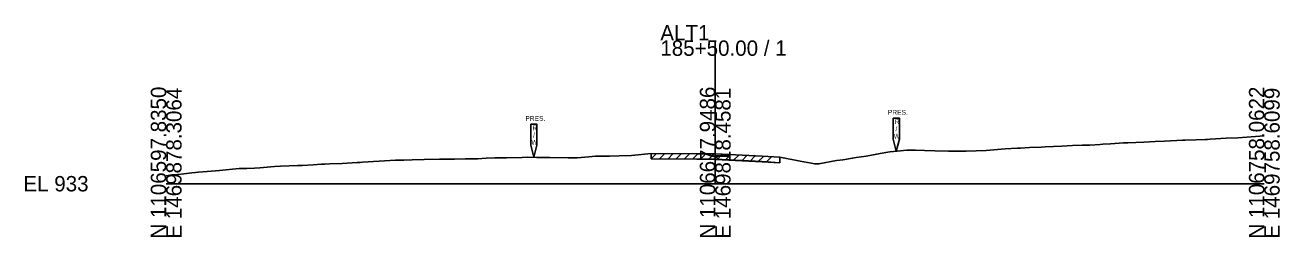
# Model space of a CAD drawing. Extents: x -26 to 2203, y -10 to 19568.
# Drawn here: x 1974.3 to 2202.8, y 7490.3 to 7528.9 of the extents above; entities that cross this region are included whole.
import ezdxf

# ---------------------------------------------------------------- set-up
doc = ezdxf.new("R2010")
doc.units = 0
for name, color, linetype in [('RD_GPK_XS_Cell', 7, 'Continuous'), ('RD_XS_ExGround', 7, 'Continuous'), ('RD_XS_ExPaveRet', 7, 'Continuous'), ('RD_XS_ExRW', 7, 'Continuous')]:
    doc.layers.add(name, color=color, linetype=linetype)

msp = doc.modelspace()

# ---------------------------------------------------------------- linework, layer by layer
at = {"layer": 'RD_GPK_XS_Cell'}
for p, q in [((2100, 7500), (2100, 7526.1)), ((2000, 7500), (2100, 7500)), ((2100, 7500), (2200, 7500))]:
    msp.add_line(p, q, dxfattribs=at)
at = {"layer": 'RD_XS_ExGround'}
msp.add_lwpolyline([(2000, 7501.43), (2001.05, 7501.62), (2002.08, 7501.67), (2003.19, 7501.77), (2004.69, 7501.98), (2005.34, 7502.05), (2005.82, 7502.11), (2007.48, 7502.23), (2009.7, 7502.39), (2013.31, 7502.75), (2014.71, 7502.79), (2016.06, 7502.82), (2017.06, 7502.88), (2019.73, 7503.12), (2020.8, 7503.19), (2023.97, 7503.3), (2024.74, 7503.33), (2026.77, 7503.43), (2028.29, 7503.57), (2028.92, 7503.59), (2029.75, 7503.62), (2032.04, 7503.69), (2034.77, 7503.87), (2035.35, 7503.85), (2035.78, 7503.91), (2038.78, 7504.09), (2039.78, 7504.14), (2041.78, 7504.28), (2043.27, 7504.31), (2044.79, 7504.38), (2047.01, 7504.42), (2049.8, 7504.46), (2050.76, 7504.48), (2052.49, 7504.48), (2054.5, 7504.54), (2054.82, 7504.54), (2056.78, 7504.56), (2058.25, 7504.63), (2059.83, 7504.69), (2061.99, 7504.72), (2064.84, 7504.8), (2065.74, 7504.83), (2067.5, 7504.8), (2069.48, 7504.77), (2069.85, 7504.77), (2073.23, 7504.71), (2074.87, 7504.73), (2076.97, 7504.89), (2078.22, 7504.99), (2079.88, 7505.03), (2080.36, 7505.03), (2080.72, 7505.04), (2082.5, 7505.05), (2084.72, 7505.14), (2088.34, 7505.52), (2096.79, 7505.47), (2100.05, 7505.44), (2108.57, 7505), (2111.75, 7504.82), (2115.49, 7504.1), (2118.13, 7503.62), (2118.48, 7503.62), (2118.87, 7503.62), (2122.11, 7504.2), (2123.23, 7504.36), (2124.99, 7504.67), (2125.65, 7504.78), (2127.51, 7505.03), (2129.4, 7505.39), (2130.01, 7505.5), (2131.8, 7505.79), (2133.14, 7505.96), (2134.89, 7506.14), (2136.46, 7506.11), (2138.09, 7506.06), (2140, 7506.02), (2142.46, 7505.92), (2143.17, 7505.92), (2144.67, 7505.91), (2145.14, 7505.92), (2145.69, 7505.94), (2149.34, 7506.08), (2152.81, 7506.34), (2155.07, 7506.48), (2155.61, 7506.5), (2157.21, 7506.57), (2159.35, 7506.66), (2160.08, 7506.69), (2163.1, 7506.84), (2165.09, 7506.96), (2166.84, 7507.01), (2168.24, 7507.03), (2170.11, 7507.16), (2170.59, 7507.2), (2172.01, 7507.29), (2174.33, 7507.42), (2174.67, 7507.44), (2175.12, 7507.46), (2178.08, 7507.54), (2180.13, 7507.67), (2181.82, 7507.78), (2185.15, 7507.92), (2185.57, 7507.93), (2187.53, 7508), (2189.31, 7508.07), (2189.67, 7508.08), (2190.16, 7508.11), (2193.06, 7508.3), (2195.17, 7508.38), (2196.8, 7508.46), (2200, 7508.7)], dxfattribs=at)
at = {"layer": 'RD_XS_ExPaveRet'}
for p, q in [((2088.34, 7505.52), (2088.34, 7504.52)), ((2088.34, 7504.53), (2089.31, 7505.51)), ((2088.34, 7504.53), (2088.34, 7505.51)), ((2089.84, 7504.51), (2090.83, 7505.5)), ((2091.34, 7504.5), (2092.33, 7505.49)), ((2092.84, 7504.49), (2093.83, 7505.48)), ((2094.34, 7504.49), (2095.33, 7505.47)), ((2095.84, 7504.48), (2096.83, 7505.47)), ((2097.34, 7504.48), (2098.31, 7505.45)), ((2098.84, 7504.47), (2099.81, 7505.44)), ((2100.34, 7504.43), (2101.28, 7505.37)), ((2101.84, 7504.35), (2102.78, 7505.29)), ((2103.34, 7504.27), (2104.28, 7505.22)), ((2104.84, 7504.19), (2105.78, 7505.14)), ((2106.34, 7504.11), (2107.28, 7505.06)), ((2088.34, 7504.53), (2088.36, 7504.54)), ((2088.34, 7504.52), (2096.79, 7504.47)), ((2088.36, 7504.54), (2096.66, 7504.49)), ((2096.66, 7504.49), (2100.07, 7504.46)), ((2096.79, 7504.47), (2100.05, 7504.44)), ((2100.05, 7504.44), (2108.57, 7504)), ((2100.07, 7504.46), (2108.46, 7504.02)), ((2107.84, 7504.04), (2108.78, 7504.98)), ((2108.46, 7504.02), (2111.75, 7503.83)), ((2108.57, 7504), (2111.75, 7503.82)), ((2109.34, 7503.97), (2110.27, 7504.9)), ((2111.75, 7504.83), (2111.75, 7503.83)), ((2111.75, 7504.82), (2111.75, 7503.82))]:
    msp.add_line(p, q, dxfattribs=at)
at = {"layer": 'RD_XS_ExRW'}
for points in [[(2132.43, 7511.95), (2133.53, 7511.95), (2133.53, 7508.12), (2132.98, 7505.93), (2132.43, 7508.12)], [(2066.43, 7510.82), (2067.53, 7510.82), (2067.53, 7507), (2066.98, 7504.81), (2066.43, 7507)]]:
    msp.add_lwpolyline(points, close=True, dxfattribs=at)

# ---------------------------------------------------------------- texts
at = {"layer": 'RD_GPK_XS_Cell'}
for s, p in [('ALT1', (2090, 7526.1)), ('185+50.00 / 1', (2090, 7523.3)), ('EL 933', (1974, 7498.6))]:
    msp.add_text(s, height=2.8, dxfattribs=at).set_placement(p)
for s, p in [('N 1106597.8350', (2000, 7490)), ('E 1469878.3064', (2002.8, 7490)), ('N 1106677.9486', (2100, 7490)), ('E 1469818.4581', (2102.8, 7490)), ('N 1106758.0622', (2200, 7490)), ('E 1469758.6099', (2202.8, 7490))]:
    msp.add_text(s, height=2.8, rotation=90, dxfattribs=at).set_placement(p)
at = {"layer": 'RD_XS_ExRW'}
for s, p in [('PRES.', (2065.43, 7511.45)), ('PRES.', (2131.44, 7512.57)), ('R', (2066.69, 7509.73)), ('R', (2132.69, 7510.86)), ('/', (2132.82, 7509.54)), ('W', (2066.51, 7507.11)), ('/', (2066.82, 7508.42)), ('W', (2132.51, 7508.23))]:
    msp.add_text(s, height=0.875, dxfattribs=at).set_placement(p)

doc.saveas('drawing.dxf')
